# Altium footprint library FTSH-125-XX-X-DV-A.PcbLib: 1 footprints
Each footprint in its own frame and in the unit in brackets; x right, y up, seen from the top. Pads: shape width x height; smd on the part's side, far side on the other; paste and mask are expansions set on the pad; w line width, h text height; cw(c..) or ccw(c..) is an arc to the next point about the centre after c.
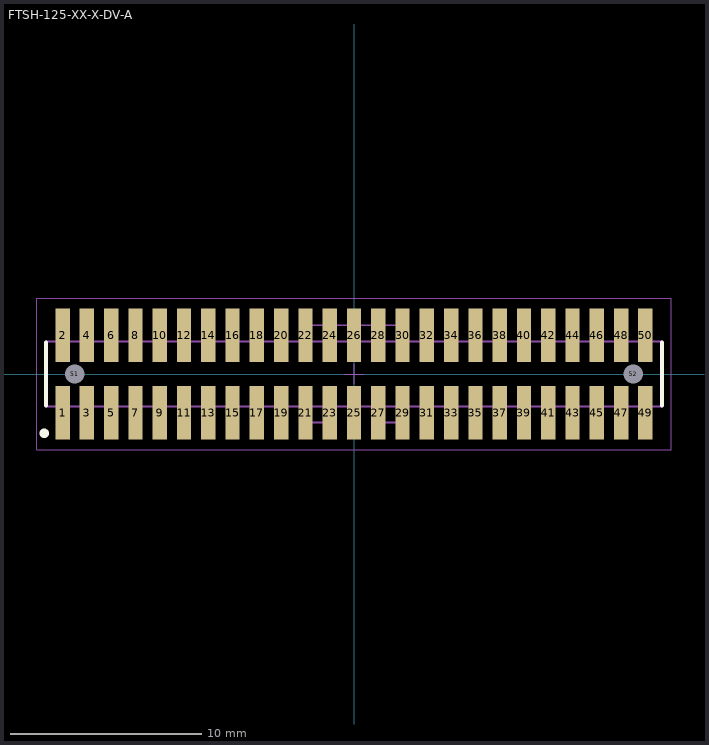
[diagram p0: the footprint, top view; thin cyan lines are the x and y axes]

## FTSH-125-XX-X-DV-A [mm] "1.27mm pitch, 100 pin, terminal strip; w/alignment pins, SMT"
height 5.97
pads (52):
  rect 0.75x2.8 smd mask+0: 1(-15.24,-2.03) 2(-15.24,2.03) 3(-13.97,-2.03) 4(-13.97,2.03) 5(-12.7,-2.03) 6(-12.7,2.03) 7(-11.43,-2.03) 8(-11.43,2.03) 9(-10.16,-2.03) 10(-10.16,2.03) 11(-8.89,-2.03) 12(-8.89,2.03) 13(-7.62,-2.03) 14(-7.62,2.03) 15(-6.35,-2.03) 16(-6.35,2.03) 17(-5.08,-2.03) 18(-5.08,2.03) 19(-3.81,-2.03) 20(-3.81,2.03) 21(-2.54,-2.03) 22(-2.54,2.03) 23(-1.27,-2.03) 24(-1.27,2.03) 25(0,-2.03) 26(0,2.03) 27(1.27,-2.03) 28(1.27,2.03) 29(2.54,-2.03) 30(2.54,2.03) 31(3.81,-2.03) 32(3.81,2.03) 33(5.08,-2.03) 34(5.08,2.03) 35(6.35,-2.03) 36(6.35,2.03) 37(7.62,-2.03) 38(7.62,2.03) 39(8.89,-2.03) 40(8.89,2.03) 41(10.16,-2.03) 42(10.16,2.03) 43(11.43,-2.03) 44(11.43,2.03) 45(12.7,-2.03) 46(12.7,2.03) 47(13.97,-2.03) 48(13.97,2.03) 49(15.24,-2.03) 50(15.24,2.03)
  round 0.5 hole 1 unplated mask+0: 51(-14.605,0) 52(14.605,0)
Top Overlay:
  circle w0.25: c-16.2,-3.1 r0.125
  lines w0.2: -16.1,-1.65 -16.1,1.65 ; 16.1,-1.65 16.1,1.65
Mechanical 12:
  lines w0.001: -16.1,-1.7 -2.55,-1.7 -2.55,-2.54 -1.1,-2.54 -1.1,-1.7 1.1,-1.7 1.1,-2.54 2.55,-2.54 2.55,-1.7 16.1,-1.7 16.1,1.7 2.55,1.7 2.55,2.55 -2.7,2.55 -2.7,1.7 -16.1,1.7 -16.1,-1.7
Mechanical 13:
  lines w0.1: -2.7,1.7 -16.1,1.7 -16.1,-1.7 -2.55,-1.7 ; -2.7,1.7 -2.7,2.55 2.55,2.55 2.55,1.7 ; -2.7,1.7 2.55,1.7 ; -2.55,-1.7 -2.55,-2.54 -1.1,-2.54 -1.1,-1.7 ; -2.55,-1.7 -1.1,-1.7 ; -1.1,-1.7 1.1,-1.7 ; 1.1,-1.7 1.1,-2.54 2.55,-2.54 2.55,-1.7 ; 1.1,-1.7 2.55,-1.7 ; 2.55,-1.7 16.1,-1.7 16.1,1.7 2.55,1.7
  text ".Designator" at 0.254,0.254 h1.52
Mechanical 15:
  lines w0.05: -0.5,0 0.5,0 ; 0,-0.5 0,0.5 ; -16.6,-3.95 16.6,-3.95 16.6,3.95 -16.6,3.95 -16.6,-3.95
